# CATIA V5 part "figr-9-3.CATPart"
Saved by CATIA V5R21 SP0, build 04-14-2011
Part number: Part1
Bounding box of the stored display mesh (mm): x -25 to 69.61, y -164.735 to 0, z 0 to 45
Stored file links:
  D:\CATIA V5R21 E-RESOURCES\CATIA-V5R21\catia-v5r21-prt\c09-catia-v5r20-prt\c09-catia-v5r21-figr-9-3.CATPart
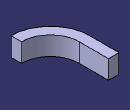
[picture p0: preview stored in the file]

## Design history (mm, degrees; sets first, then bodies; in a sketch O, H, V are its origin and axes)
Body1 (main body)
  Sketch1 on xy-plane, origin (0, 0, 0), H (1, 0, 0), V (0, 1, 0)
    line L1 (0, 0) -> (0, -70.1255)
    arc A1 centre (69.6095, -70.1255) radius 69.6095 from (0, -70.1255) to (69.6095, -139.7351) ccw
    vertical: L1 V
    tangency: A1 L1
  Sketch2 on zx-plane, origin (0, 0, 0), H (-1, 0, 0), V (0, 0, 1)
    point P1 (0, 0)
    line L1 (0, 0) -> (25, 0)
    line L2 (25, 0) -> (25, 45)
    line L3 (25, 45) -> (0, 45)
    line L4 (0, 45) -> (0, 0)
    length L3 = 25
    length L2 = 45
    coincidence: P1 H, P1 O
    horizontal: L1 H, L3 H
    vertical: L2 V, L4 V
  Rib1: profile Sketch2, centre curve Sketch1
